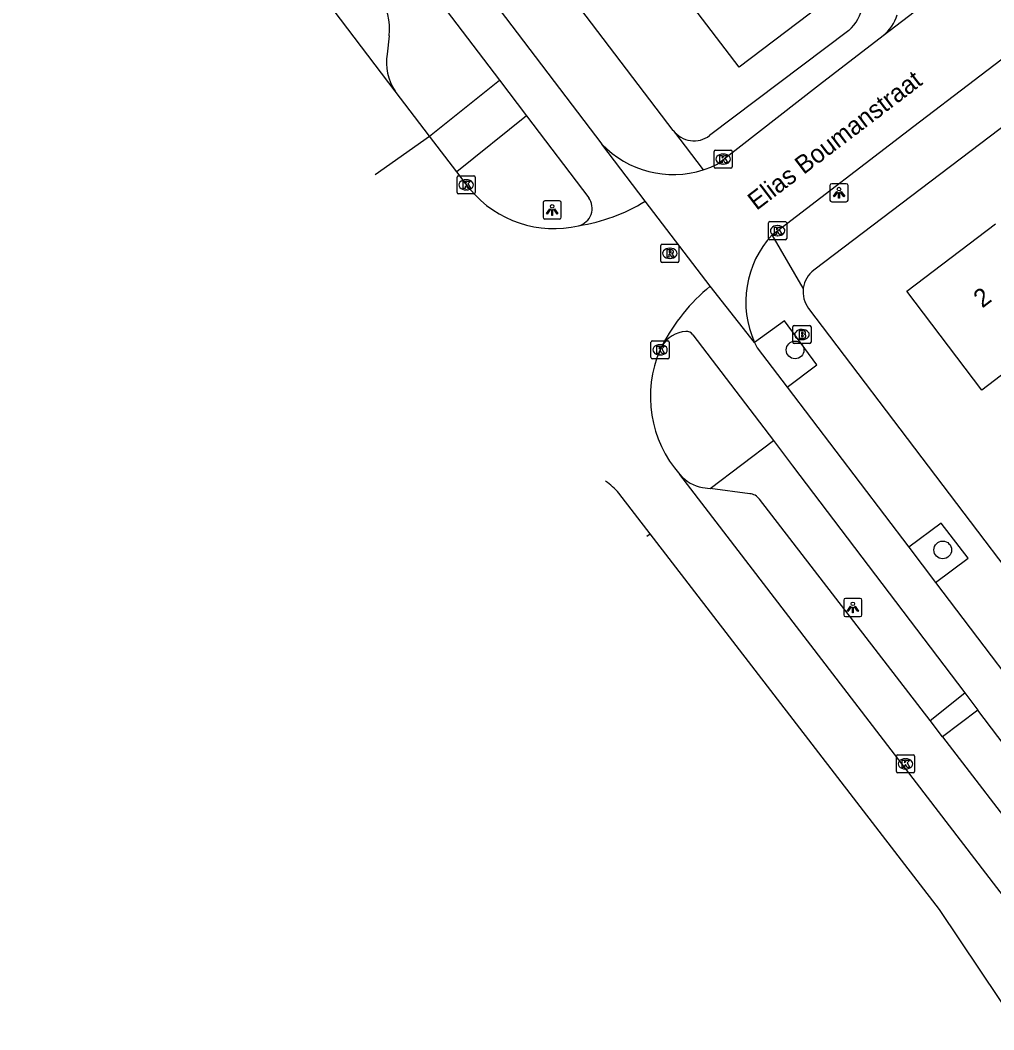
# Model space of a CAD drawing. Extents: x 160037 to 160839, y 385326 to 386441.
# Drawn here: x 160258.5 to 160312.3, y 385719.4 to 385775.1 of the extents above; entities that cross this region are included whole.
import ezdxf

# ---------------------------------------------------------------- set-up
doc = ezdxf.new("R2010")
doc.units = 0
for name, color, linetype in [('IMGEO_Boom', 7, 'Continuous'), ('IMGEO_Brandkraan', 7, 'Continuous'), ('IMGEO_Fietspad_gesloten', 7, 'Continuous'), ('IMGEO_Kolk', 7, 'Continuous'), ('IMGEO_Lichtpunt', 7, 'Continuous'), ('IMGEO_Openbare_ruimte_label', 7, 'Continuous'), ('IMGEO_Pand', 7, 'Continuous'), ('IMGEO_Pand_nummerreeks', 7, 'Continuous'), ('IMGEO_Parkeervlak_open', 7, 'Continuous'), ('IMGEO_Rijbaan_lokaal_gesloten', 7, 'Continuous'), ('IMGEO_Rijbaan_lokaal_open', 7, 'Continuous'), ('IMGEO_Rioolput', 7, 'Continuous'), ('IMGEO_Verkeerseiland_groen', 7, 'Continuous'), ('IMGEO_Voetpad_open', 7, 'Continuous')]:
    doc.layers.add(name, color=color, linetype=linetype)

msp = doc.modelspace()

# ---------------------------------------------------------------- linework, layer by layer
at = {"layer": 'IMGEO_Boom'}
for centre in [(160301.307, 385756.946), (160309.456, 385745.914)]:
    msp.add_circle(centre, 0.489, dxfattribs=at)
at = {"layer": 'IMGEO_Brandkraan'}
for p, q in [((160301.261, 385758.296), (160302.113, 385758.296)), ((160301.186, 385757.37), (160301.186, 385758.222)), ((160301.674, 385758.076), (160301.699, 385758.076)), ((160302.187, 385758.222), (160302.187, 385757.37)), ((160302.113, 385757.296), (160301.261, 385757.296)), ((160301.697, 385757.516), (160301.672, 385757.516))]:
    msp.add_line(p, q, dxfattribs=at)
for points in [[(160301.261, 385758.296), (160302.113, 385758.296)], [(160301.186, 385757.37), (160301.186, 385758.222)], [(160301.534, 385757.996), (160301.534, 385757.596), (160301.747, 385757.596)], [(160301.765, 385757.996), (160301.534, 385757.996)], [(160301.713, 385757.915), (160301.659, 385757.915), (160301.659, 385757.839)], [(160301.659, 385757.839), (160301.712, 385757.839)], [(160301.721, 385757.763), (160301.659, 385757.763), (160301.659, 385757.682)], [(160301.659, 385757.682), (160301.721, 385757.682)], [(160302.187, 385758.222), (160302.187, 385757.37)], [(160302.113, 385757.296), (160301.261, 385757.296)]]:
    msp.add_lwpolyline(points, dxfattribs=at)
for centre, radius, start, end in [((160301.263, 385758.22), 0.0765, 91.552, 178.448), ((160301.263, 385758.22), 0.0765, 91.552, 178.448), ((160302.111, 385758.22), 0.0765, 1.552, 88.448), ((160302.111, 385758.22), 0.0765, 1.552, 88.448), ((160301.714, 385757.877), 0.0379, 267.8285, 90.9355), ((160301.722, 385757.722), 0.0404, 269.8759, 90.5077), ((160301.769, 385757.851), 0.145, 59.4692, 91.5367), ((160301.794, 385757.898), 0.0922, 285.5137, 58.1501), ((160301.799, 385757.706), 0.105, 301.3115, 78.989), ((160301.263, 385757.372), 0.0765, 181.552, 268.448), ((160301.263, 385757.372), 0.0765, 181.552, 268.448), ((160301.753, 385757.847), 0.251, 268.6676, 293.5347), ((160302.111, 385757.372), 0.0765, 271.552, 358.448), ((160302.111, 385757.372), 0.0765, 271.552, 358.448)]:
    msp.add_arc(centre, radius, start, end, dxfattribs=at)
for centre, major_axis, ratio, start_param, end_param in [((160301.673, 385757.796), (-0.387, 0.002), 0.722429, 4.712389, 7.853982), ((160301.698, 385757.796), (-0.39, 0.002), 0.717154, 1.570796, 4.712389)]:
    msp.add_ellipse(centre, major_axis=major_axis, ratio=ratio, start_param=start_param, end_param=end_param, dxfattribs=at)
at = {"layer": 'IMGEO_Fietspad_gesloten'}
for points in [[(160278.156, 385780.813), (160284.988, 385771.823)], [(160284.323, 385776.61), (160290.63, 385768.308)], [(160284.988, 385771.823), (160286.475, 385769.866)], [(160286.475, 385769.866), (160289.911, 385765.345)], [(160295.669, 385757.788), (160300.105, 385751.947)], [(160299.069, 385757.362), (160299.218, 385757.06), (160300.869, 385754.887)], [(160300.869, 385754.887), (160307.578, 385746.06)], [(160300.105, 385751.947), (160301.166, 385750.55), (160310.672, 385738.033)], [(160307.578, 385746.06), (160309.056, 385744.115)], [(160309.056, 385744.115), (160315.956, 385735.036)], [(160310.672, 385738.033), (160311.402, 385737.072)], [(160321.032, 385724.394), (160311.402, 385737.072)]]:
    msp.add_lwpolyline(points, dxfattribs=at)
for centre, radius, start, end in [((160289.114, 385764.759), 0.989, 284.1651, 36.316), ((160295.352, 385756.342), 1.622, 92.7288, 149.0188), ((160295.319, 385757.528), 0.436, 36.5924, 95.7527)]:
    msp.add_arc(centre, radius, start, end, dxfattribs=at)
at = {"layer": 'IMGEO_Kolk'}
for p, q in [((160296.839, 385767.051), (160296.839, 385767.903)), ((160296.914, 385767.977), (160297.766, 385767.977)), ((160297.327, 385767.757), (160297.352, 385767.757)), ((160297.84, 385767.903), (160297.84, 385767.051)), ((160297.35, 385767.197), (160297.325, 385767.197)), ((160297.766, 385766.977), (160296.914, 385766.977)), ((160282.652, 385765.63), (160282.652, 385766.482)), ((160282.727, 385766.556), (160283.579, 385766.556)), ((160283.14, 385766.336), (160283.165, 385766.336)), ((160283.653, 385766.482), (160283.653, 385765.63)), ((160283.579, 385765.556), (160282.727, 385765.556)), ((160283.163, 385765.776), (160283.138, 385765.776)), ((160299.842, 385763.099), (160299.842, 385763.951)), ((160299.917, 385764.025), (160300.769, 385764.025)), ((160300.33, 385763.805), (160300.355, 385763.805)), ((160300.843, 385763.951), (160300.843, 385763.099)), ((160300.353, 385763.245), (160300.328, 385763.245)), ((160300.769, 385763.025), (160299.917, 385763.025)), ((160293.351, 385756.53), (160293.351, 385757.382)), ((160293.426, 385757.456), (160294.278, 385757.456)), ((160293.839, 385757.236), (160293.864, 385757.236)), ((160294.352, 385757.382), (160294.352, 385756.53)), ((160293.862, 385756.676), (160293.837, 385756.676)), ((160294.278, 385756.456), (160293.426, 385756.456)), ((160306.901, 385733.687), (160306.901, 385734.539)), ((160306.976, 385734.613), (160307.828, 385734.613)), ((160307.389, 385734.393), (160307.414, 385734.393)), ((160307.902, 385734.539), (160307.902, 385733.687)), ((160307.412, 385733.833), (160307.387, 385733.833)), ((160307.828, 385733.613), (160306.976, 385733.613))]:
    msp.add_line(p, q, dxfattribs=at)
for points in [[(160296.839, 385767.051), (160296.839, 385767.903)], [(160296.914, 385767.977), (160297.766, 385767.977)], [(160297.84, 385767.903), (160297.84, 385767.051)], [(160297.16, 385767.677), (160297.283, 385767.677), (160297.283, 385767.526), (160297.413, 385767.677), (160297.577, 385767.677), (160297.431, 385767.526), (160297.584, 385767.277), (160297.432, 385767.277), (160297.347, 385767.441), (160297.283, 385767.374), (160297.283, 385767.277), (160297.16, 385767.277), (160297.16, 385767.677)], [(160297.766, 385766.977), (160296.914, 385766.977)], [(160282.652, 385765.63), (160282.652, 385766.482)], [(160282.727, 385766.556), (160283.579, 385766.556)], [(160282.973, 385766.256), (160283.096, 385766.256), (160283.096, 385766.105), (160283.226, 385766.256), (160283.39, 385766.256), (160283.244, 385766.105), (160283.397, 385765.856), (160283.245, 385765.856), (160283.16, 385766.02), (160283.096, 385765.953), (160283.096, 385765.856), (160282.973, 385765.856), (160282.973, 385766.256)], [(160283.653, 385766.482), (160283.653, 385765.63)], [(160283.579, 385765.556), (160282.727, 385765.556)], [(160299.842, 385763.099), (160299.842, 385763.951)], [(160299.917, 385764.025), (160300.769, 385764.025)], [(160300.843, 385763.951), (160300.843, 385763.099)], [(160300.163, 385763.725), (160300.286, 385763.725), (160300.286, 385763.574), (160300.416, 385763.725), (160300.58, 385763.725), (160300.434, 385763.574), (160300.587, 385763.325), (160300.435, 385763.325), (160300.35, 385763.489), (160300.286, 385763.422), (160300.286, 385763.325), (160300.163, 385763.325), (160300.163, 385763.725)], [(160300.769, 385763.025), (160299.917, 385763.025)], [(160293.351, 385756.53), (160293.351, 385757.382)], [(160293.426, 385757.456), (160294.278, 385757.456)], [(160293.672, 385757.156), (160293.795, 385757.156), (160293.795, 385757.005), (160293.925, 385757.156), (160294.089, 385757.156), (160293.943, 385757.005), (160294.096, 385756.756), (160293.944, 385756.756), (160293.859, 385756.92), (160293.795, 385756.853), (160293.795, 385756.756), (160293.672, 385756.756), (160293.672, 385757.156)], [(160294.352, 385757.382), (160294.352, 385756.53)], [(160294.278, 385756.456), (160293.426, 385756.456)], [(160306.901, 385733.687), (160306.901, 385734.539)], [(160306.976, 385734.613), (160307.828, 385734.613)], [(160307.222, 385734.313), (160307.345, 385734.313), (160307.345, 385734.162), (160307.475, 385734.313), (160307.639, 385734.313), (160307.493, 385734.162), (160307.646, 385733.913), (160307.494, 385733.913), (160307.409, 385734.077), (160307.345, 385734.01), (160307.345, 385733.913), (160307.222, 385733.913), (160307.222, 385734.313)], [(160307.902, 385734.539), (160307.902, 385733.687)], [(160307.828, 385733.613), (160306.976, 385733.613)]]:
    msp.add_lwpolyline(points, dxfattribs=at)
for centre, start, end in [((160296.916, 385767.901), 91.552, 178.448), ((160296.916, 385767.901), 91.552, 178.448), ((160297.764, 385767.901), 1.552, 88.448), ((160297.764, 385767.901), 1.552, 88.448), ((160296.916, 385767.053), 181.552, 268.448), ((160296.916, 385767.053), 181.552, 268.448), ((160297.764, 385767.053), 271.552, 358.448), ((160297.764, 385767.053), 271.552, 358.448), ((160282.729, 385766.48), 91.552, 178.448), ((160282.729, 385766.48), 91.552, 178.448), ((160283.577, 385766.48), 1.552, 88.448), ((160283.577, 385766.48), 1.552, 88.448), ((160282.729, 385765.632), 181.552, 268.448), ((160282.729, 385765.632), 181.552, 268.448), ((160283.577, 385765.632), 271.552, 358.448), ((160283.577, 385765.632), 271.552, 358.448), ((160299.919, 385763.949), 91.552, 178.448), ((160299.919, 385763.949), 91.552, 178.448), ((160300.767, 385763.949), 1.552, 88.448), ((160300.767, 385763.949), 1.552, 88.448), ((160299.919, 385763.101), 181.552, 268.448), ((160299.919, 385763.101), 181.552, 268.448), ((160300.767, 385763.101), 271.552, 358.448), ((160300.767, 385763.101), 271.552, 358.448), ((160293.428, 385757.38), 91.552, 178.448), ((160293.428, 385757.38), 91.552, 178.448), ((160294.276, 385757.38), 1.552, 88.448), ((160294.276, 385757.38), 1.552, 88.448), ((160293.428, 385756.532), 181.552, 268.448), ((160293.428, 385756.532), 181.552, 268.448), ((160294.276, 385756.532), 271.552, 358.448), ((160294.276, 385756.532), 271.552, 358.448), ((160306.978, 385734.537), 91.552, 178.448), ((160306.978, 385734.537), 91.552, 178.448), ((160307.826, 385734.537), 1.552, 88.448), ((160307.826, 385734.537), 1.552, 88.448), ((160306.978, 385733.689), 181.552, 268.448), ((160306.978, 385733.689), 181.552, 268.448), ((160307.826, 385733.689), 271.552, 358.448), ((160307.826, 385733.689), 271.552, 358.448)]:
    msp.add_arc(centre, 0.0765, start, end, dxfattribs=at)
for centre, major_axis, ratio, start_param, end_param in [((160297.326, 385767.477), (-0.387, 0.002), 0.722429, 4.712389, 7.853982), ((160297.351, 385767.477), (-0.39, 0.002), 0.717154, 1.570796, 4.712389), ((160283.139, 385766.056), (-0.387, 0.002), 0.722429, 4.712389, 7.853982), ((160283.164, 385766.056), (-0.39, 0.002), 0.717154, 1.570796, 4.712389), ((160300.329, 385763.525), (-0.387, 0.002), 0.722429, 4.712389, 7.853982), ((160300.354, 385763.525), (-0.39, 0.002), 0.717154, 1.570796, 4.712389), ((160293.838, 385756.956), (-0.387, 0.002), 0.722429, 4.712389, 7.853982), ((160293.863, 385756.956), (-0.39, 0.002), 0.717154, 1.570796, 4.712389), ((160307.388, 385734.113), (-0.387, 0.002), 0.722429, 4.712389, 7.853982), ((160307.413, 385734.113), (-0.39, 0.002), 0.717154, 1.570796, 4.712389)]:
    msp.add_ellipse(centre, major_axis=major_axis, ratio=ratio, start_param=start_param, end_param=end_param, dxfattribs=at)
at = {"layer": 'IMGEO_Lichtpunt'}
for p, q in [((160304.134, 385766.118), (160303.326, 385766.118)), ((160304.134, 385766.118), (160303.326, 385766.118)), ((160303.232, 385766.023), (160303.232, 385765.216)), ((160303.232, 385766.023), (160303.232, 385765.216)), ((160304.228, 385765.216), (160304.228, 385766.023)), ((160304.228, 385765.216), (160304.228, 385766.023)), ((160287.396, 385765.073), (160287.396, 385764.266)), ((160287.396, 385765.073), (160287.396, 385764.266)), ((160288.298, 385765.168), (160287.49, 385765.168)), ((160288.298, 385765.168), (160287.49, 385765.168)), ((160288.392, 385764.266), (160288.392, 385765.073)), ((160288.392, 385764.266), (160288.392, 385765.073)), ((160303.326, 385765.122), (160304.134, 385765.122)), ((160303.326, 385765.122), (160304.134, 385765.122)), ((160287.49, 385764.172), (160288.298, 385764.172)), ((160287.49, 385764.172), (160288.298, 385764.172)), ((160304.897, 385743.237), (160304.089, 385743.237)), ((160304.897, 385743.237), (160304.089, 385743.237)), ((160303.995, 385743.142), (160303.995, 385742.335)), ((160303.995, 385743.142), (160303.995, 385742.335)), ((160304.991, 385742.335), (160304.991, 385743.142)), ((160304.991, 385742.335), (160304.991, 385743.142)), ((160304.089, 385742.241), (160304.897, 385742.241)), ((160304.089, 385742.241), (160304.897, 385742.241))]:
    msp.add_line(p, q, dxfattribs=at)
for points in [[(160303.606, 385765.687), (160303.645, 385765.659), (160303.457, 385765.397), (160303.419, 385765.424), (160303.606, 385765.687)], [(160303.708, 385765.639), (160303.755, 385765.639), (160303.755, 385765.317), (160303.708, 385765.317), (160303.708, 385765.639)], [(160303.818, 385765.659), (160303.856, 385765.686), (160304.043, 385765.424), (160304.004, 385765.396), (160303.818, 385765.659)], [(160287.77, 385764.737), (160287.809, 385764.709), (160287.621, 385764.447), (160287.583, 385764.474), (160287.77, 385764.737)], [(160287.872, 385764.689), (160287.919, 385764.689), (160287.919, 385764.367), (160287.872, 385764.367), (160287.872, 385764.689)], [(160287.982, 385764.709), (160288.02, 385764.736), (160288.207, 385764.474), (160288.168, 385764.446), (160287.982, 385764.709)], [(160304.369, 385742.806), (160304.408, 385742.778), (160304.22, 385742.516), (160304.182, 385742.543), (160304.369, 385742.806)], [(160304.471, 385742.758), (160304.518, 385742.758), (160304.518, 385742.436), (160304.471, 385742.436), (160304.471, 385742.758)], [(160304.581, 385742.778), (160304.619, 385742.805), (160304.806, 385742.543), (160304.767, 385742.515), (160304.581, 385742.778)]]:
    msp.add_lwpolyline(points, dxfattribs=at)
for centre in [(160303.731, 385765.821), (160287.895, 385764.871), (160304.494, 385742.94)]:
    msp.add_circle(centre, 0.0994, dxfattribs=at)
for centre, start, end in [((160303.326, 385766.023), 90, 180), ((160303.326, 385766.023), 90, 180), ((160304.134, 385766.023), 0, 90), ((160304.134, 385766.023), 0, 90), ((160287.49, 385765.073), 90, 180), ((160287.49, 385765.073), 90, 180), ((160288.298, 385765.073), 0, 90), ((160288.298, 385765.073), 0, 90), ((160303.326, 385765.216), 180, 270), ((160303.326, 385765.216), 180, 270), ((160304.134, 385765.216), 270, 0), ((160304.134, 385765.216), 270, 360), ((160287.49, 385764.266), 180, 270), ((160287.49, 385764.266), 180, 270), ((160288.298, 385764.266), 270, 0), ((160288.298, 385764.266), 270, 360), ((160304.089, 385743.142), 90, 180), ((160304.089, 385743.142), 90, 180), ((160304.897, 385743.142), 0, 90), ((160304.897, 385743.142), 0, 90), ((160304.089, 385742.335), 180, 270), ((160304.089, 385742.335), 180, 270), ((160304.897, 385742.335), 270, 0), ((160304.897, 385742.335), 270, 360)]:
    msp.add_arc(centre, 0.0946, start, end, dxfattribs=at)
at = {"layer": 'IMGEO_Pand'}
for points in [[(160304.666, 385777.443), (160298.219, 385772.539), (160294.413, 385777.543)], [(160316.515, 385758.458), (160311.612, 385754.734), (160307.475, 385760.183), (160312.377, 385763.906)]]:
    msp.add_lwpolyline(points, dxfattribs=at)
at = {"layer": 'IMGEO_Parkeervlak_open'}
for points in [[(160278.902, 385774.282), (160278.781, 385773.271)], [(160296.195, 385749.355), (160296.619, 385749.3)], [(160298.806, 385749.016), (160296.619, 385749.3)], [(160308.762, 385736.501), (160299.335, 385748.714)], [(160309.449, 385735.606), (160314.276, 385729.312)]]:
    msp.add_lwpolyline(points, dxfattribs=at)
for centre, radius, start, end in [((160275.582, 385774.631), 3.338, 353.9992, 34.5656), ((160281.543, 385772.802), 2.802, 170.3553, 214.0949), ((160296.538, 385751.384), 2.058, 219.5717, 260.4039), ((160298.773, 385748.343), 0.673, 33.3894, 87.1675)]:
    msp.add_arc(centre, radius, start, end, dxfattribs=at)
at = {"layer": 'IMGEO_Rijbaan_lokaal_gesloten'}
for points in [[(160279.223, 385771.231), (160228.526, 385837.944)], [(160281.119, 385768.748), (160279.223, 385771.231)], [(160278.119, 385766.625), (160281.119, 385768.748)], [(160282.625, 385766.776), (160281.119, 385768.748)], [(160283.372, 385765.797), (160282.625, 385766.776)], [(160296.619, 385760.458), (160293.027, 385765.153)], [(160293.852, 385756.956), (160293.962, 385757.177)], [(160314.443, 385724.679), (160294.952, 385750.073)], [(160293.298, 385746.808), (160291.573, 385749.046)], [(160313.726, 385719.442), (160309.274, 385726.08), (160293.298, 385746.808)]]:
    msp.add_lwpolyline(points, dxfattribs=at)
for centre, radius, start, end in [((160287.99, 385769.67), 6.027, 219.9875, 283.1024), ((160287.825, 385773.612), 9.93, 278.8711, 301.5931), ((160303.191, 385752.42), 10.383, 129.2685, 152.7294), ((160299.78, 385754.374), 6.466, 156.4625, 221.6973), ((160289.095, 385747.046), 3.184, 38.9122, 56.6893), ((160289.088, 385747.039), 3.194, 56.6476, 56.6522)]:
    msp.add_arc(centre, radius, start, end, dxfattribs=at)
at = {"layer": 'IMGEO_Rijbaan_lokaal_open'}
for points in [[(160300.038, 385763.291), (160307.863, 385769.299), (160317.856, 385776.929), (160339.609, 385793.352)], [(160306.172, 385774.291), (160329.097, 385791.8)], [(160297.059, 385767.227), (160302.66, 385771.599), (160306.172, 385774.291)], [(160293.027, 385765.153), (160290.63, 385768.308)], [(160299.069, 385757.362), (160296.619, 385760.458)]]:
    msp.add_lwpolyline(points, dxfattribs=at)
for centre, radius, start, end in [((160294.57, 385772.08), 5.455, 223.7508, 287.7489), ((160294.571, 385772.068), 5.443, 287.7813, 297.2021), ((160303.989, 385759.602), 5.406, 136.9628, 204.4732)]:
    msp.add_arc(centre, radius, start, end, dxfattribs=at)
at = {"layer": 'IMGEO_Rioolput'}
for p, q in [((160293.893, 385761.851), (160293.893, 385762.703)), ((160293.968, 385762.777), (160294.82, 385762.777)), ((160294.894, 385762.703), (160294.894, 385761.851)), ((160294.381, 385762.557), (160294.406, 385762.557)), ((160294.82, 385761.777), (160293.968, 385761.777)), ((160294.404, 385761.997), (160294.379, 385761.997))]:
    msp.add_line(p, q, dxfattribs=at)
for points in [[(160293.893, 385761.851), (160293.893, 385762.703)], [(160293.968, 385762.777), (160294.82, 385762.777)], [(160294.894, 385762.703), (160294.894, 385761.851)], [(160294.482, 385762.475), (160294.23, 385762.477), (160294.23, 385762.077)], [(160294.23, 385762.077), (160294.354, 385762.077), (160294.354, 385762.239), (160294.365, 385762.239)], [(160294.408, 385762.396), (160294.354, 385762.396), (160294.354, 385762.315)], [(160294.354, 385762.315), (160294.406, 385762.315)], [(160294.412, 385762.21), (160294.483, 385762.077), (160294.623, 385762.077), (160294.558, 385762.203)], [(160294.82, 385761.777), (160293.968, 385761.777)]]:
    msp.add_lwpolyline(points, dxfattribs=at)
for centre, radius, start, end in [((160293.97, 385762.701), 0.0765, 91.552, 178.448), ((160293.97, 385762.701), 0.0765, 91.552, 178.448), ((160294.818, 385762.701), 0.0765, 1.552, 88.448), ((160294.818, 385762.701), 0.0765, 1.552, 88.448), ((160294.364, 385762.186), 0.0533, 26.0293, 88.6989), ((160294.39, 385762.504), 0.19, 274.7715, 282.9687), ((160294.414, 385762.3), 0.0964, 77.0061, 93.1865), ((160294.428, 385762.357), 0.0378, 276.6634, 79.6772), ((160294.481, 385762.365), 0.109, 350.3612, 89.416), ((160294.479, 385762.365), 0.112, 277.5842, 350.9817), ((160294.463, 385762.15), 0.108, 29.5134, 73.7905), ((160293.97, 385761.853), 0.0765, 181.552, 268.448), ((160293.97, 385761.853), 0.0765, 181.552, 268.448), ((160294.818, 385761.853), 0.0765, 271.552, 358.448), ((160294.818, 385761.853), 0.0765, 271.552, 358.448)]:
    msp.add_arc(centre, radius, start, end, dxfattribs=at)
for centre, major_axis, ratio, start_param, end_param in [((160294.38, 385762.277), (-0.387, 0.002), 0.722429, 4.712389, 7.853982), ((160294.405, 385762.277), (-0.39, 0.002), 0.717154, 1.570796, 4.712389)]:
    msp.add_ellipse(centre, major_axis=major_axis, ratio=ratio, start_param=start_param, end_param=end_param, dxfattribs=at)
at = {"layer": 'IMGEO_Verkeerseiland_groen'}
for points in [[(160296.619, 385749.3), (160300.105, 385751.947)], [(160293.119, 385746.682), (160293.12, 385746.682), (160293.298, 385746.808)]]:
    msp.add_lwpolyline(points, dxfattribs=at)
at = {"layer": 'IMGEO_Voetpad_open'}
for points in [[(160294.583, 385769.052), (160231.475, 385851.922)], [(160355.696, 385801.806), (160302.341, 385761.357)], [(160304.268, 385774.578), (160296.589, 385768.772)], [(160281.119, 385768.748), (160284.988, 385771.823)], [(160286.475, 385769.866), (160282.625, 385766.776)], [(160294.583, 385769.052), (160294.598, 385769.03), (160296.233, 385766.885)], [(160301.756, 385760.356), (160300.038, 385763.291)], [(160302.051, 385759.235), (160309.061, 385750), (160315.254, 385741.841)], [(160300.869, 385754.887), (160302.514, 385756.128), (160300.729, 385758.557), (160299.069, 385757.362)], [(160309.056, 385744.115), (160310.855, 385745.455), (160309.372, 385747.391), (160307.578, 385746.06)], [(160308.762, 385736.501), (160310.672, 385738.033)], [(160311.402, 385737.072), (160309.449, 385735.606)], [(160309.449, 385735.606), (160308.762, 385736.501)]]:
    msp.add_lwpolyline(points, dxfattribs=at)
for centre, radius, start, end in [((160302.888, 385776.23), 2.152, 309.8772, 34.3052), ((160304.66, 385776.157), 2.402, 309.018, 342.4518), ((160295.726, 385769.913), 1.431, 217.0018, 307.1061), ((160303.256, 385760.151), 1.513, 127.1759, 172.2187), ((160303.256, 385760.151), 1.514, 172.234, 217.2531)]:
    msp.add_arc(centre, radius, start, end, dxfattribs=at)

# ---------------------------------------------------------------- texts
at = {"layer": 'IMGEO_Openbare_ruimte_label'}
msp.add_text('Elias Boumanstraat', height=1, rotation=37.2823, dxfattribs=at).set_placement((160299.177, 385764.613))
at = {"layer": 'IMGEO_Pand_nummerreeks'}
msp.add_text('2', height=1, rotation=37.2132, dxfattribs=at).set_placement((160311.639, 385759.227))

doc.saveas('drawing.dxf')
